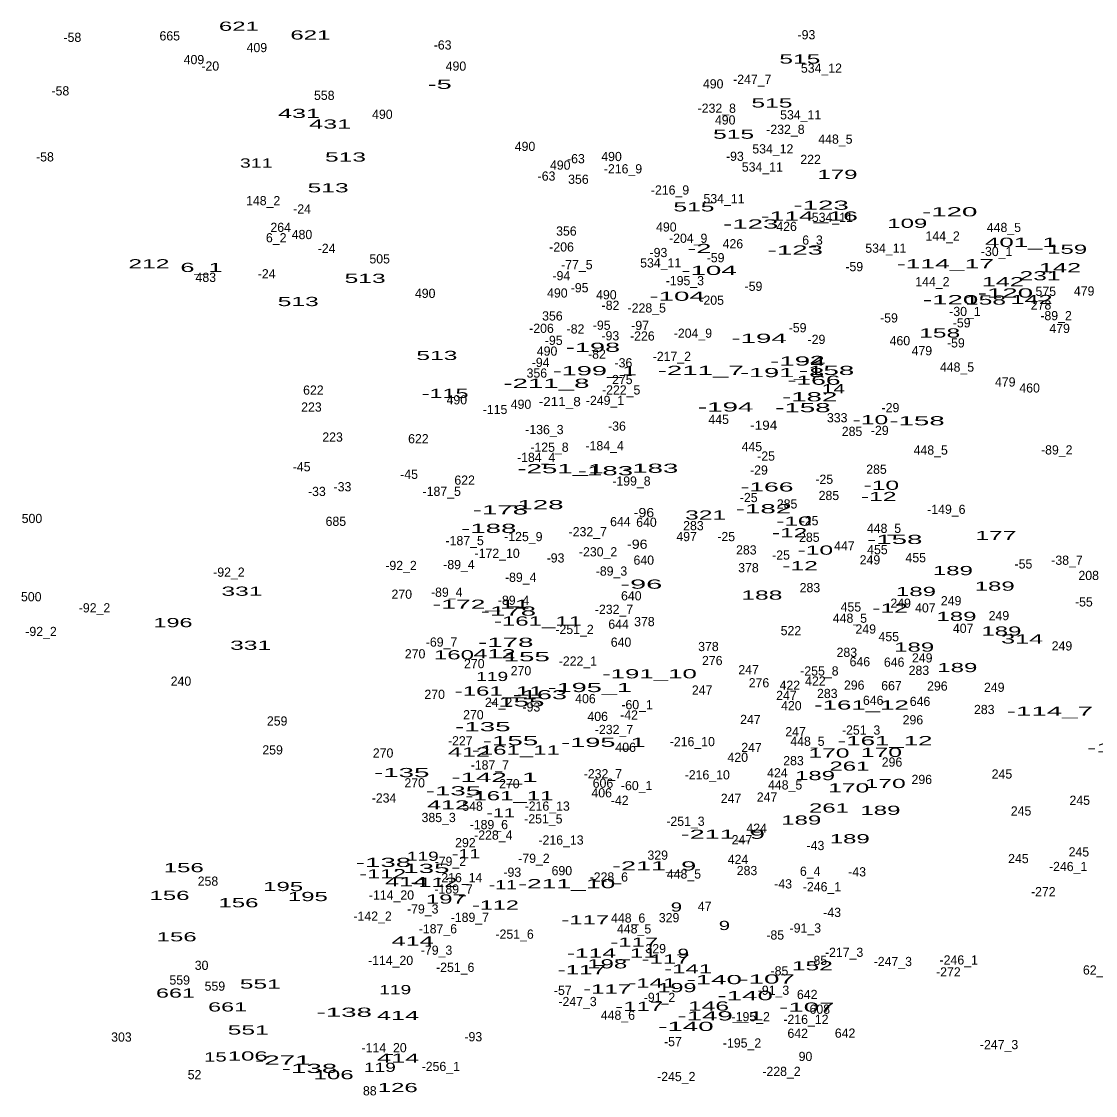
# Model space of a CAD drawing. Extents: x -661742 to -657295, y -1002932 to -996888.
# Drawn here: x -660007.5 to -659540.4, y -1000306.3 to -999839.2 of the extents above; entities that cross this region are included whole.
import ezdxf
from ezdxf.enums import TextEntityAlignment as Align

# ---------------------------------------------------------------- set-up
doc = ezdxf.new("R2010")
doc.units = 0
doc.header["$LTSCALE"] = 1.6
doc.layers.add('24', color=7, linetype='Continuous')

msp = doc.modelspace()

# ---------------------------------------------------------------- texts
at = {"layer": '24'}
for s, width, p in [('621', 1.95, (-659912.953, -999843.25)), ('621', 1.95, (-659881.863, -999847.04)), ('515', 2, (-659669.017, -999857.51)), ('-5', 2.2, (-659825.624, -999868.5)), ('515', 2, (-659681.137, -999876.61)), ('431', 2.05, (-659886.803, -999881.17)), ('431', 2.05, (-659873.263, -999885.81)), ('515', 2, (-659697.807, -999890.19)), ('513', 2, (-659866.597, -999900.13)), ('311', 1.6, (-659905.404, -999902.75)), ('179', 1.95, (-659652.647, -999907.69)), ('513', 2, (-659874.157, -999913.52)), ('515', 2, (-659715.067, -999921.8)), ('-123', 2.25, (-659659.741, -999921.09)), ('-120', 2.25, (-659603.837, -999923.95)), ('-123', 2.25, (-659690.371, -999929.24)), ('-114_16', 2.15, (-659664.875, -999925.8)), ('109', 1.95, (-659622.279, -999928.95)), ('401_1', 2.1, (-659572.857, -999937.21)), ('-2', 2.2, (-659712.714, -999939.91)), ('-123', 2.25, (-659670.981, -999940.58)), ('159', 1.95, (-659552.753, -999940.24)), ('212', 2, (-659952.097, -999946.58)), ('-114_17', 2.15, (-659605.695, -999946.56)), ('6_1', 2.05, (-659929.233, -999948.16)), ('-104', 2.25, (-659708.512, -999949.44)), ('231', 2, (-659564.557, -999951.77)), ('142', 2.05, (-659555.853, -999948.27)), ('513', 2, (-659858.067, -999952.89)), ('142', 2.05, (-659580.713, -999954.36)), ('-104', 2.25, (-659722.372, -999960.68)), ('-120', 2.25, (-659579.607, -999959.25)), ('513', 2, (-659887.147, -999962.97)), ('-120', 2.25, (-659603.447, -999962.16)), ('158', 2, (-659588.267, -999962.35)), ('142', 2.05, (-659568.233, -999962.1)), ('-194', 2.25, (-659686.741, -999978.96)), ('158', 2, (-659608.187, -999976.66)), ('-198', 2.2, (-659758.945, -999982.89)), ('513', 2, (-659826.857, -999986.43)), ('-194', 2.25, (-659669.871, -999988.85)), ('-2', 2.2, (-659663.404, -999988.62)), ('-199_1', 2.2, (-659758.137, -999993.07)), ('-211_7', 2.25, (-659712.123, -999992.94)), ('-191_8', 2.2, (-659676.683, -999993.88)), ('-158', 2.25, (-659657.391, -999992.95)), ('-211_8', 2.25, (-659779.217, -999998.54)), ('-166', 2.15, (-659662.819, -999997.2)), ('-115', 1.9, (-659823.257, -1000002.94)), ('14', 1.7, (-659654.403, -1000000.89)), ('-211_8', 1.1, (-659773.419, -1000006.49)), ('-182', 2.25, (-659664.741, -1000004.4)), ('-194', 2.25, (-659701.281, -1000008.83)), ('-158', 2.25, (-659667.681, -1000009.13)), ('-194', 1.1, (-659684.711, -1000016.78)), ('-10', 2, (-659638.317, -1000014.37)), ('-158', 2.25, (-659618.051, -1000014.85)), ('-251_1', 2.25, (-659773.117, -1000035.66)), ('-183', 2.25, (-659753.551, -1000036.55)), ('-183', 2.25, (-659733.871, -1000035.48)), ('-166', 2.15, (-659683.279, -1000043.6)), ('-10', 2, (-659633.567, -1000042.88)), ('-12', 2, (-659634.701, -1000047.78)), ('-178', 2.25, (-659799.235, -1000053.59)), ('-128', 2.25, (-659783.801, -1000051.33)), ('-96', 1.15, (-659736.799, -1000054.77)), ('-182', 2.25, (-659684.811, -1000053.08)), ('321', 2, (-659709.977, -1000055.8)), ('-10', 2, (-659671.567, -1000058.49)), ('-188', 2.25, (-659804.311, -1000061.63)), ('-12', 2, (-659673.471, -1000063.49)), ('177', 2, (-659583.747, -1000064.75)), ('-96', 1.15, (-659739.699, -1000068.53)), ('-158', 2.25, (-659627.741, -1000066.44)), ('-10', 2, (-659662.267, -1000071.1)), ('-12', 2, (-659668.911, -1000077.89)), ('189', 1.95, (-659602.443, -1000079.99)), ('-96', 2.35, (-659737.923, -1000085.89)), ('189', 1.95, (-659584.263, -1000086.76)), ('331', 2, (-659911.617, -1000088.96)), ('188', 2, (-659685.527, -1000090.65)), ('189', 1.95, (-659618.493, -1000089.08)), ('-172_11', 2.15, (-659807.669, -1000094.63)), ('-12', 2, (-659629.751, -1000096.31)), ('-178', 2.25, (-659795.745, -1000097.61)), ('-161_11', 1.95, (-659782.895, -1000101.94)), ('189', 1.95, (-659600.893, -1000099.92)), ('196', 1.9, (-659941.607, -1000102.61)), ('189', 1.95, (-659581.363, -1000106.3)), ('-178', 2.25, (-659796.905, -1000111.19)), ('314', 2.05, (-659572.313, -1000109.72)), ('331', 2, (-659907.837, -1000112.47)), ('412', 2.05, (-659801.793, -1000116.15)), ('189', 1.95, (-659619.273, -1000113.27)), ('160', 1.95, (-659819.419, -1000116.62)), ('-155', 2.25, (-659789.791, -1000117.46)), ('-191_10', 2.1, (-659734.405, -1000124.88)), ('189', 1.95, (-659600.513, -1000122.17)), ('119', 1.55, (-659802.789, -1000126.04)), ('-161_11', 1.95, (-659799.955, -1000132.37)), ('-163', 2.2, (-659782.045, -1000133.95)), ('-195_1', 2.2, (-659760.353, -1000130.84)), ('-155', 2.25, (-659792.121, -1000137.11)), ('-161_12', 2.1, (-659642.219, -1000138.44)), ('-114_7', 2.25, (-659560.248, -1000141.15)), ('-135', 2.25, (-659806.851, -1000147.86)), ('-161_11', 1.95, (-659792.495, -1000158.06)), ('-155', 2.25, (-659794.831, -1000153.99)), ('-195_1', 2.2, (-659754.433, -1000154.69)), ('-161_12', 2.1, (-659631.939, -1000153.96)), ('-114_7', 2.25, (-659525.358, -1000157.05)), ('412', 2.05, (-659812.913, -1000158.88)), ('170', 2, (-659656.339, -1000159.33)), ('170', 2, (-659633.519, -1000159.04)), ('261', 1.95, (-659647.443, -1000165.03)), ('-135', 2.25, (-659842.131, -1000167.84)), ('-142_1', 2.25, (-659801.803, -1000169.88)), ('189', 1.95, (-659662.403, -1000169.14)), ('-135', 2.25, (-659819.651, -1000175.78)), ('170', 2, (-659647.739, -1000174.51)), ('170', 2, (-659631.879, -1000172.58)), ('-161_11', 1.95, (-659795.305, -1000177.91)), ('412', 2.05, (-659822.003, -1000181.9)), ('-11', 1.6, (-659799.127, -1000185.38)), ('261', 1.95, (-659656.333, -1000183.22)), ('189', 1.95, (-659633.973, -1000184.24)), ('189', 1.95, (-659668.393, -1000188.49)), ('-211_9', 2.2, (-659702.523, -1000194.66)), ('189', 1.95, (-659647.313, -1000196.62)), ('119', 1.55, (-659832.959, -1000204.22)), ('-11', 1.6, (-659814.147, -1000203.11)), ('156', 1.95, (-659936.933, -1000209.18)), ('-138', 2.25, (-659850.061, -1000206.91)), ('-135', 2.25, (-659833.411, -1000209.53)), ('-211_9', 2.2, (-659732.383, -1000208.43)), ('-112', 1.9, (-659850.387, -1000211.87)), ('195', 1.95, (-659893.703, -1000217.39)), ('414', 2.05, (-659840.199, -1000215.29)), ('-112', 1.9, (-659828.097, -1000215.56)), ('-11', 1.6, (-659798.157, -1000216.62)), ('-211_10', 2.15, (-659770.37, -1000216.15)), ('156', 1.95, (-659943.123, -1000221.27)), ('195', 1.95, (-659882.973, -1000221.75)), ('197', 1.95, (-659822.947, -1000222.85)), ('156', 1.95, (-659913.143, -1000224.46)), ('-112', 1.9, (-659801.357, -1000225.45)), ('9', 1.65, (-659722.696, -1000226.31)), ('-117', 1.95, (-659762.311, -1000231.88)), ('9', 1.65, (-659701.816, -1000234.34)), ('156', 1.95, (-659940.023, -1000239.26)), ('414', 2.05, (-659837.389, -1000241.09)), ('-117', 1.95, (-659740.981, -1000241.58)), ('-114_11', 2, (-659750.736, -1000246.35)), ('9', 1.65, (-659719.706, -1000246.43)), ('198', 1.95, (-659752.773, -1000251.01)), ('-117', 1.95, (-659727.411, -1000248.95)), ('-117', 1.95, (-659763.861, -1000253.6)), ('-141', 1.95, (-659717.562, -1000253.22)), ('152', 2, (-659663.567, -1000251.87)), ('551', 2, (-659903.647, -1000259.82)), ('-141', 1.95, (-659733.172, -1000259.33)), ('-140', 2.25, (-659706.242, -1000257.87)), ('-107', 2.25, (-659683.231, -1000257.63)), ('661', 1.9, (-659940.537, -1000263.73)), ('119', 1.55, (-659844.959, -1000262.23)), ('-117', 1.95, (-659752.811, -1000261.94)), ('199', 1.9, (-659722.467, -1000261.35)), ('-140', 2.25, (-659692.772, -1000264.85)), ('661', 1.9, (-659917.857, -1000269.75)), ('-117', 1.95, (-659738.851, -1000269.51)), ('146', 2, (-659708.718, -1000269.36)), ('-107', 2.25, (-659665.981, -1000269.85)), ('-138', 2.25, (-659867.121, -1000272.07)), ('414', 2.05, (-659843.769, -1000273.48)), ('-149_1', 2.25, (-659703.488, -1000273.65)), ('-140', 2.25, (-659718.552, -1000278.23)), ('551', 2, (-659908.887, -1000279.8)), ('15', 1.65, (-659923.157, -1000291.51)), ('106', 1.95, (-659909.099, -1000291.1)), ('-271', 2.25, (-659893.855, -1000292.87)), ('414', 2.05, (-659843.679, -1000292.05)), ('-138', 2.25, (-659882.241, -1000296.51)), ('119', 1.55, (-659851.629, -1000296.02)), ('106', 1.95, (-659871.769, -1000299.22)), ('126', 1.95, (-659843.873, -1000304.83))]:
    msp.add_text(s, height=4, dxfattribs=dict(at, width=width)).set_placement(p, align=Align.CENTER)
for s, p in [('-58', (-659985.365, -999848.08)), ('665', (-659943.018, -999847.44)), ('-93', (-659666.14, -999846.96)), ('409', (-659905.141, -999852.54)), ('-63', (-659824.36, -999851.4)), ('409', (-659932.501, -999857.76)), ('-20', (-659925.409, -999860.56)), ('490', (-659818.571, -999860.6)), ('534_12', (-659659.613, -999861.48)), ('490', (-659706.701, -999868.31)), ('-247_7', (-659689.688, -999866.33)), ('-58', (-659990.595, -999871.36)), ('558', (-659875.827, -999873.31)), ('490', (-659850.561, -999881.54)), ('-232_8', (-659705.132, -999878.91)), ('534_11', (-659668.637, -999881.78)), ('490', (-659701.471, -999884.02)), ('-232_8', (-659675.272, -999888.1)), ('490', (-659788.521, -999895.51)), ('534_12', (-659680.743, -999896.58)), ('448_5', (-659653.534, -999892.36)), ('-58', (-659997.285, -999900.06)), ('-63', (-659766.39, -999900.85)), ('490', (-659750.901, -999899.92)), ('-93', (-659697.25, -999899.81)), ('222', (-659664.327, -999901.17)), ('490', (-659773.201, -999903.65)), ('-216_9', (-659745.917, -999905.26)), ('534_11', (-659685.307, -999904.47)), ('-63', (-659779.18, -999908.42)), ('356', (-659765.303, -999909.8)), ('-216_9', (-659725.467, -999914.48)), ('148_2', (-659902.393, -999919.12)), ('534_11', (-659701.977, -999918.24)), ('-24', (-659885.469, -999922.71)), ('534_11', (-659654.867, -999926.39)), ('264', (-659894.777, -999930.72)), ('480', (-659885.515, -999933.84)), ('356', (-659770.523, -999932.32)), ('490', (-659727.061, -999930.56)), ('426', (-659674.767, -999930.32)), ('448_5', (-659580.254, -999930.76)), ('6_2', (-659896.731, -999935.25)), ('-204_9', (-659717.546, -999935.46)), ('426', (-659698.127, -999937.86)), ('6_3', (-659663.491, -999936.26)), ('144_2', (-659606.898, -999934.49)), ('-24', (-659874.809, -999939.87)), ('-206', (-659772.624, -999939.24)), ('-93', (-659730.5, -999941.67)), ('534_11', (-659631.607, -999939.77)), ('-30_1', (-659583.43, -999941.21)), ('505', (-659851.731, -999944.42)), ('-77_5', (-659765.994, -999946.95)), ('534_11', (-659729.507, -999946.17)), ('-59', (-659705.65, -999943.93)), ('-59', (-659645.35, -999947.81)), ('483', (-659927.351, -999952.46)), ('-24', (-659900.879, -999950.92)), ('-94', (-659772.725, -999951.75)), ('-95', (-659764.78, -999956.99)), ('-195_3', (-659719.002, -999953.89)), ('-59', (-659689.17, -999956.34)), ('144_2', (-659611.348, -999954.32)), ('490', (-659831.941, -999959.42)), ('490', (-659774.461, -999959.25)), ('490', (-659753.131, -999960.04)), ('575', (-659562.043, -999958.57)), ('479', (-659545.363, -999958.4)), ('-82', (-659751.345, -999964.62)), ('-228_5', (-659735.582, -999965.76)), ('-205', (-659707.359, -999962.41)), ('278', (-659564.113, -999964.47)), ('356', (-659776.613, -999969.24)), ('-59', (-659630.23, -999970.1)), ('-30_1', (-659597.19, -999967.3)), ('-89_2', (-659557.578, -999969.12)), ('-206', (-659781.354, -999974.63)), ('-82', (-659766.565, -999974.9)), ('-95', (-659755.18, -999973.28)), ('-97', (-659738.465, -999973.38)), ('-59', (-659669.98, -999974.38)), ('-59', (-659598.63, -999972.24)), ('479', (-659556.023, -999974.69)), ('-95', (-659776.04, -999979.87)), ('-93', (-659751.42, -999977.88)), ('-226', (-659737.5, -999977.95)), ('-204_9', (-659715.506, -999976.76)), ('-29', (-659661.78, -999979.46)), ('460', (-659625.501, -999980.01)), ('490', (-659778.921, -999984.54)), ('479', (-659615.933, -999984.39)), ('-59', (-659601.15, -999980.96)), ('-94', (-659781.735, -999989.47)), ('-82', (-659757.235, -999985.85)), ('-36', (-659745.72, -999989.63)), ('-217_2', (-659724.662, -999986.82)), ('356', (-659783.383, -999994.1)), ('448_5', (-659600.644, -999991.5)), ('275', (-659746.213, -999996.91)), ('479', (-659579.683, -999997.97)), ('622', (-659880.563, -1000001.5)), ('-222_5', (-659746.702, -1000001.43)), ('460', (-659569.081, -1000000.56)), ('490', (-659818.181, -1000005.72)), ('490', (-659790.261, -1000007.66)), ('-249_1', (-659753.736, -1000005.99)), ('223', (-659881.407, -1000008.87)), ('-115', (-659801.551, -1000009.92)), ('-29', (-659629.6, -1000009.13)), ('-36', (-659748.53, -1000017.17)), ('445', (-659704.316, -1000014.24)), ('333', (-659652.757, -1000013.52)), ('223', (-659872.217, -1000021.93)), ('622', (-659834.903, -1000022.64)), ('-136_3', (-659780.092, -1000018.66)), ('285', (-659646.307, -1000019.47)), ('-29', (-659634.25, -1000019.03)), ('-125_8', (-659777.886, -1000026.34)), ('-184_4', (-659753.905, -1000025.7)), ('445', (-659689.866, -1000026.07)), ('-184_4', (-659783.665, -1000030.74)), ('-25', (-659683.685, -1000030.19)), ('448_5', (-659612.084, -1000027.58)), ('-89_2', (-659557.288, -1000027.5)), ('-45', (-659885.659, -1000034.84)), ('-29', (-659686.79, -1000036.28)), ('285', (-659635.667, -1000035.91)), ('-45', (-659838.939, -1000038.13)), ('622', (-659814.783, -1000040.66)), ('-199_8', (-659742.237, -1000041.06)), ('-25', (-659658.385, -1000040.28)), ('-33', (-659879.035, -1000045.58)), ('-33', (-659867.905, -1000043.54)), ('-187_5', (-659824.742, -1000045.53)), ('-25', (-659691.245, -1000048.23)), ('285', (-659656.367, -1000047.33)), ('285', (-659674.547, -1000051)), ('-149_6', (-659605.291, -1000053.35)), ('500', (-660002.955, -1000057.33)), ('685', (-659870.783, -1000058.56)), ('644', (-659747.051, -1000058.7)), ('640', (-659735.711, -1000058.97)), ('-25', (-659664.775, -1000058.32)), ('-232_7', (-659761.238, -1000063.1)), ('283', (-659715.287, -1000060.45)), ('448_5', (-659632.404, -1000061.62)), ('-187_5', (-659814.762, -1000066.96)), ('-125_9', (-659789.242, -1000065.2)), ('497', (-659718.243, -1000065.2)), ('-25', (-659701.035, -1000065.2)), ('285', (-659664.877, -1000065.51)), ('447', (-659649.631, -1000069.26)), ('-172_10', (-659800.649, -1000072.46)), ('-230_2', (-659756.756, -1000071.83)), ('283', (-659692.267, -1000071)), ('-25', (-659677.185, -1000073.25)), ('455', (-659635.261, -1000070.89)), ('-92_2', (-659842.448, -1000077.77)), ('-89_4', (-659817.252, -1000077.38)), ('-93', (-659775.25, -1000074.5)), ('640', (-659736.871, -1000075.45)), ('378', (-659691.353, -1000078.77)), ('249', (-659638.507, -1000075.32)), ('455', (-659618.591, -1000074.38)), ('-55', (-659571.755, -1000077.12)), ('-38_7', (-659552.818, -1000075.49)), ('-92_2', (-659917.288, -1000080.68)), ('-89_4', (-659790.402, -1000082.91)), ('-89_3', (-659750.928, -1000080.21)), ('208', (-659543.381, -1000082.11)), ('283', (-659664.617, -1000087.4)), ('500', (-660003.255, -1000091.36)), ('270', (-659842.117, -1000090.27)), ('-89_4', (-659822.582, -1000089.41)), ('640', (-659742.301, -1000090.97)), ('-92_2', (-659975.748, -1000096.19)), ('-89_4', (-659793.502, -1000092.9)), ('-232_7', (-659749.828, -1000096.85)), ('455', (-659646.801, -1000095.81)), ('249', (-659625.157, -1000094.18)), ('407', (-659614.421, -1000096.21)), ('249', (-659603.207, -1000093.11)), ('-55', (-659545.485, -1000093.61)), ('378', (-659736.603, -1000102.18)), ('448_5', (-659647.224, -1000100.7)), ('249', (-659582.417, -1000099.6)), ('-92_2', (-659999.008, -1000106.47)), ('-251_2', (-659766.976, -1000105.57)), ('644', (-659747.831, -1000103.3)), ('522', (-659672.877, -1000106.11)), ('249', (-659640.337, -1000105.4)), ('407', (-659597.981, -1000105.11)), ('-69_7', (-659824.828, -1000111.09)), ('640', (-659746.761, -1000111.13)), ('455', (-659630.321, -1000108.71)), ('270', (-659836.317, -1000116.19)), ('378', (-659708.753, -1000113.02)), ('283', (-659648.567, -1000115.55)), ('249', (-659555.007, -1000112.75)), ('270', (-659810.587, -1000120.45)), ('-222_1', (-659765.516, -1000119.34)), ('276', (-659707.088, -1000119.12)), ('646', (-659642.903, -1000119.62)), ('646', (-659627.983, -1000119.82)), ('249', (-659615.787, -1000117.97)), ('270', (-659790.287, -1000123.55)), ('247', (-659691.277, -1000123.07)), ('-255_8', (-659660.502, -1000123.64)), ('283', (-659617.227, -1000123.38)), ('240', (-659938.145, -1000128.09)), ('276', (-659686.778, -1000128.79)), ('422', (-659673.361, -1000129.86)), ('422', (-659662.241, -1000128.02)), ('296', (-659645.358, -1000129.8)), ('667', (-659629.153, -1000130.03)), ('296', (-659609.198, -1000130.19)), ('270', (-659827.807, -1000133.8)), ('247', (-659711.487, -1000131.97)), ('247', (-659674.837, -1000134.29)), ('283', (-659657.067, -1000133.44)), ('249', (-659584.447, -1000130.75)), ('24_2', (-659800.01, -1000137.28)), ('-93', (-659785.75, -1000139.31)), ('406', (-659762.241, -1000135.69)), ('-60_1', (-659739.786, -1000138.29)), ('420', (-659672.695, -1000138.74)), ('646', (-659637.093, -1000136.41)), ('646', (-659616.733, -1000136.89)), ('270', (-659810.977, -1000142.7)), ('406', (-659756.921, -1000143.42)), ('-42', (-659743.269, -1000142.78)), ('283', (-659588.797, -1000140.41)), ('259', (-659896.313, -1000145.4)), ('247', (-659690.497, -1000144.74)), ('296', (-659619.838, -1000144.89)), ('-232_7', (-659749.828, -1000149.11)), ('247', (-659670.867, -1000150.06)), ('-251_3', (-659642.356, -1000149.35)), ('259', (-659898.293, -1000157.98)), ('-227', (-659816.681, -1000154.03)), ('406', (-659744.741, -1000156.86)), ('-216_10', (-659715.759, -1000154.37)), ('247', (-659690.017, -1000156.92)), ('448_5', (-659665.704, -1000154.22)), ('270', (-659850.237, -1000159.34)), ('420', (-659695.995, -1000161.19)), ('283', (-659671.767, -1000162.66)), ('-187_7', (-659803.827, -1000164.53)), ('296', (-659628.928, -1000163.27)), ('-232_7', (-659754.658, -1000168.36)), ('-216_10', (-659709.269, -1000168.82)), ('424', (-659678.776, -1000167.95)), ('296', (-659615.968, -1000170.82)), ('245', (-659581.111, -1000168.47)), ('270', (-659836.507, -1000172.3)), ('270', (-659795.317, -1000172.69)), ('406', (-659755.181, -1000176.64)), ('606', (-659754.622, -1000172.45)), ('-60_1', (-659739.976, -1000173.49)), ('448_5', (-659675.404, -1000173.21)), ('-234', (-659849.829, -1000178.88)), ('-42', (-659747.339, -1000179.92)), ('247', (-659698.917, -1000179.05)), ('247', (-659683.247, -1000178.48)), ('245', (-659547.261, -1000179.88)), ('548', (-659811.331, -1000182.47)), ('-216_13', (-659778.875, -1000182.43)), ('245', (-659572.791, -1000184.53)), ('385_3', (-659826.075, -1000187.38)), ('-189_6', (-659804.267, -1000190.46)), ('-251_5', (-659780.546, -1000187.97)), ('-251_3', (-659718.746, -1000189.01)), ('-228_4', (-659802.317, -1000195.02)), ('424', (-659687.766, -1000192.04)), ('292', (-659814.443, -1000198.31)), ('-216_13', (-659772.865, -1000197.17)), ('247', (-659694.177, -1000197.04)), ('-43', (-659662.219, -1000199.56)), ('329', (-659730.813, -1000203.76)), ('245', (-659547.651, -1000202.33)), ('-79_2', (-659820.984, -1000206.45)), ('-79_2', (-659784.634, -1000205.14)), ('424', (-659695.886, -1000205.58)), ('245', (-659573.951, -1000205.23)), ('-246_1', (-659552.326, -1000208.7)), ('-216_14', (-659816.889, -1000213.54)), ('-93', (-659794.06, -1000211.17)), ('690', (-659772.502, -1000210.51)), ('-228_6', (-659752.088, -1000213.25)), ('448_5', (-659719.404, -1000211.95)), ('283', (-659691.977, -1000210.45)), ('6_4', (-659664.505, -1000210.76)), ('-43', (-659644.089, -1000211.01)), ('258', (-659926.407, -1000215.06)), ('-189_7', (-659819.597, -1000218.48)), ('-43', (-659676.269, -1000216.24)), ('-246_1', (-659659.376, -1000217.5)), ('-114_20', (-659846.597, -1000221.1)), ('-272', (-659563.121, -1000219.62)), ('-79_3', (-659833.004, -1000227.15)), ('47', (-659710.397, -1000226.01)), ('-142_2', (-659854.81, -1000230.28)), ('-189_7', (-659812.517, -1000230.8)), ('448_6', (-659743.659, -1000231.09)), ('329', (-659725.873, -1000230.94)), ('-43', (-659654.949, -1000228.65)), ('-187_6', (-659826.407, -1000235.79)), ('448_5', (-659741.084, -1000235.81)), ('-91_3', (-659666.612, -1000235.45)), ('-251_6', (-659793.052, -1000238.11)), ('-85', (-659679.705, -1000238.48)), ('-79_3', (-659826.994, -1000245.09)), ('329', (-659731.673, -1000244.39)), ('-217_3', (-659649.752, -1000246)), ('30', (-659929.171, -1000251.67)), ('-114_20', (-659846.987, -1000249.53)), ('-85', (-659661.005, -1000249.53)), ('-247_3', (-659628.562, -1000250.01)), ('-246_1', (-659599.906, -1000249.33)), ('-251_6', (-659818.872, -1000252.53)), ('-85', (-659677.865, -1000254.09)), ('-272', (-659604.411, -1000254.53)), ('62_15', (-659538.444, -1000253.68)), ('559', (-659938.703, -1000258.08)), ('559', (-659923.393, -1000260.72)), ('-57', (-659772.091, -1000262.54)), ('-91_2', (-659730.042, -1000265.6)), ('-91_3', (-659680.472, -1000262.51)), ('642', (-659665.807, -1000264.35)), ('-247_3', (-659765.672, -1000267.42)), ('448_6', (-659748.119, -1000273.37)), ('-195_2', (-659690.362, -1000274)), ('608', (-659660.317, -1000270.75)), ('-216_12', (-659666.355, -1000275.15)), ('303', (-659964.041, -1000282.86)), ('-93', (-659811.02, -1000282.73)), ('642', (-659669.927, -1000281.22)), ('642', (-659649.327, -1000281.17)), ('-114_20', (-659849.797, -1000287.48)), ('-57', (-659724.201, -1000284.85)), ('-195_2', (-659694.142, -1000285.44)), ('-247_3', (-659582.362, -1000286.14)), ('90', (-659666.547, -1000291.3)), ('-256_1', (-659825.152, -1000295.65)), ('-228_2', (-659676.982, -1000297.8)), ('52', (-659932.247, -1000299.21)), ('-245_2', (-659722.737, -1000300.04)), ('88', (-659856.027, -1000306.24))]:
    msp.add_text(s, height=4, dxfattribs=at).set_placement(p, align=Align.CENTER)

doc.saveas('drawing.dxf')
